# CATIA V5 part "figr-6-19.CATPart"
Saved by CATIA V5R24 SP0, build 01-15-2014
Part number: Part1
Bounding box of the stored display mesh (mm): x 0 to 150, y -70 to 70, z -150 to 69.804
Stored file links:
  D:\KAVITA\CATIA V5-6R2014 Project_ Kavita\CATIA V5-6R2014_partfiles\Partfiles\c06_catia_v5-6r2014_prt\figr-6-19.CATPart
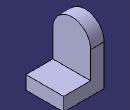
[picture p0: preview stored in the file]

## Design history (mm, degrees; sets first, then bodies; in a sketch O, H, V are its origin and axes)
Body1 (main body)
  Sketch1 on yz-plane, origin (0, 0, 0), H (0, 1, 0), V (0, 0, 1)
    arc A1 centre (0, 0) radius 70 from (70, 0) to (-70, 0) ccw
    point P1 (70, 0)
    point P2 (-70, 0)
    line L1 (-70, 0) -> (-70, -150)
    line L2 (-70, -150) -> (70, -150)
    line L3 (70, -150) -> (70, 0)
    construction circle A2 centre (0, 0) radius 37.5
    radius A1 = 70
    radius A2 = 37.5
    distance O L2 = 150
    coincidence: P1 H, P2 H
    tangency: L1 A1, L3 A1
    horizontal: L2 H
  Pad1: profile Sketch1, direction (1, 0, 0), length 50
  Sketch2 on face of Pad1, origin (50, 0, 0), H (0, 1, 0), V (0, 0, 1)
    line L1 (-70, -150) -> (70, -150)
    line L2 (70, -150) -> (70, -100)
    line L3 (70, -100) -> (-70, -100)
    line L4 (-70, -100) -> (-70, -150)
    reference projected line E1 (-70, -150) -> (70, -150) from edge [face of Pad1 | face of Pad1]
    reference projected line E2 (-70, 0) -> (-70, -150) from edge [face of Pad1 | face of Pad1]
    reference projected line E3 (70, -150) -> (70, 0) from edge [face of Pad1 | face of Pad1]
    length L2 = 50
    horizontal: L1 H, L3 H
    vertical: L2 V, L4 V
    coincidence: L1 E1, E2 L4, L2 E3
  Pad2: profile Sketch2, direction (1, 0, 0), length 100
